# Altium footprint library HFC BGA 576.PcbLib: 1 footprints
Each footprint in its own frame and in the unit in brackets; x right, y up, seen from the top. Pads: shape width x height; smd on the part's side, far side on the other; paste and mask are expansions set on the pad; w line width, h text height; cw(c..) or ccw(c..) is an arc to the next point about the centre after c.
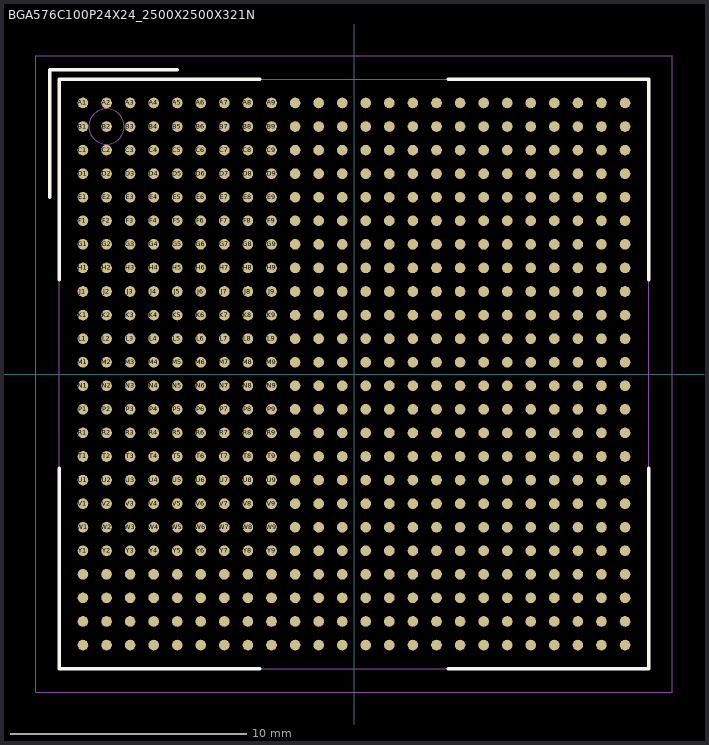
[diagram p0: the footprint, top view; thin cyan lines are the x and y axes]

## BGA576C100P24X24_2500X2500X321N [mm] "576-BGA, collapsing, 1.00 mm pitch, 25.00 X 25.00 X 3.21 mm body"
height 3.21
pads (576):
  round 0.45 smd mask+0.05: A1(-11.5,11.5) A2(-10.5,11.5) A3(-9.5,11.5) A4(-8.5,11.5) A5(-7.5,11.5) A6(-6.5,11.5) A7(-5.5,11.5) A8(-4.5,11.5) A9(-3.5,11.5) A10(-2.5,11.5) A11(-1.5,11.5) A12(-0.5,11.5) A13(0.5,11.5) A14(1.5,11.5) A15(2.5,11.5) A16(3.5,11.5) A17(4.5,11.5) A18(5.5,11.5) A19(6.5,11.5) A20(7.5,11.5) A21(8.5,11.5) A22(9.5,11.5) A23(10.5,11.5) A24(11.5,11.5) AA1(-11.5,-8.5) AA2(-10.5,-8.5) AA3(-9.5,-8.5) AA4(-8.5,-8.5) AA5(-7.5,-8.5) AA6(-6.5,-8.5) AA7(-5.5,-8.5) AA8(-4.5,-8.5) AA9(-3.5,-8.5) AA10(-2.5,-8.5) AA11(-1.5,-8.5) AA12(-0.5,-8.5) AA13(0.5,-8.5) AA14(1.5,-8.5) AA15(2.5,-8.5) AA16(3.5,-8.5) AA17(4.5,-8.5) AA18(5.5,-8.5) AA19(6.5,-8.5) AA20(7.5,-8.5) AA21(8.5,-8.5) AA22(9.5,-8.5) AA23(10.5,-8.5) AA24(11.5,-8.5) AB1(-11.5,-9.5) AB2(-10.5,-9.5) AB3(-9.5,-9.5) AB4(-8.5,-9.5) AB5(-7.5,-9.5) AB6(-6.5,-9.5) AB7(-5.5,-9.5) AB8(-4.5,-9.5) AB9(-3.5,-9.5) AB10(-2.5,-9.5) AB11(-1.5,-9.5) AB12(-0.5,-9.5) AB13(0.5,-9.5) AB14(1.5,-9.5) AB15(2.5,-9.5) AB16(3.5,-9.5) AB17(4.5,-9.5) AB18(5.5,-9.5) AB19(6.5,-9.5) AB20(7.5,-9.5) AB21(8.5,-9.5) AB22(9.5,-9.5) AB23(10.5,-9.5) AB24(11.5,-9.5) AC1(-11.5,-10.5) AC2(-10.5,-10.5) AC3(-9.5,-10.5) AC4(-8.5,-10.5) AC5(-7.5,-10.5) AC6(-6.5,-10.5) AC7(-5.5,-10.5) AC8(-4.5,-10.5) AC9(-3.5,-10.5) AC10(-2.5,-10.5) AC11(-1.5,-10.5) AC12(-0.5,-10.5) AC13(0.5,-10.5) AC14(1.5,-10.5) AC15(2.5,-10.5) AC16(3.5,-10.5) AC17(4.5,-10.5) AC18(5.5,-10.5) AC19(6.5,-10.5) AC20(7.5,-10.5) AC21(8.5,-10.5) AC22(9.5,-10.5) AC23(10.5,-10.5) AC24(11.5,-10.5) AD1(-11.5,-11.5) AD2(-10.5,-11.5) AD3(-9.5,-11.5) AD4(-8.5,-11.5) AD5(-7.5,-11.5) AD6(-6.5,-11.5) AD7(-5.5,-11.5) AD8(-4.5,-11.5) AD9(-3.5,-11.5) AD10(-2.5,-11.5) AD11(-1.5,-11.5) AD12(-0.5,-11.5) AD13(0.5,-11.5) AD14(1.5,-11.5) AD15(2.5,-11.5) AD16(3.5,-11.5) AD17(4.5,-11.5) AD18(5.5,-11.5) AD19(6.5,-11.5) AD20(7.5,-11.5) AD21(8.5,-11.5) AD22(9.5,-11.5) AD23(10.5,-11.5) AD24(11.5,-11.5) B1(-11.5,10.5) B2(-10.5,10.5) B3(-9.5,10.5) B4(-8.5,10.5) B5(-7.5,10.5) B6(-6.5,10.5) B7(-5.5,10.5) B8(-4.5,10.5) B9(-3.5,10.5) B10(-2.5,10.5) B11(-1.5,10.5) B12(-0.5,10.5) B13(0.5,10.5) B14(1.5,10.5) B15(2.5,10.5) B16(3.5,10.5) B17(4.5,10.5) B18(5.5,10.5) B19(6.5,10.5) B20(7.5,10.5) B21(8.5,10.5) B22(9.5,10.5) B23(10.5,10.5) B24(11.5,10.5) C1(-11.5,9.5) C2(-10.5,9.5) C3(-9.5,9.5) C4(-8.5,9.5) C5(-7.5,9.5) C6(-6.5,9.5) C7(-5.5,9.5) C8(-4.5,9.5) C9(-3.5,9.5) C10(-2.5,9.5) C11(-1.5,9.5) C12(-0.5,9.5) C13(0.5,9.5) C14(1.5,9.5) C15(2.5,9.5) C16(3.5,9.5) C17(4.5,9.5) C18(5.5,9.5) C19(6.5,9.5) C20(7.5,9.5) C21(8.5,9.5) C22(9.5,9.5) C23(10.5,9.5) C24(11.5,9.5) D1(-11.5,8.5) D2(-10.5,8.5) D3(-9.5,8.5) D4(-8.5,8.5) D5(-7.5,8.5) D6(-6.5,8.5) D7(-5.5,8.5) D8(-4.5,8.5) D9(-3.5,8.5) D10(-2.5,8.5) D11(-1.5,8.5) D12(-0.5,8.5) D13(0.5,8.5) D14(1.5,8.5) D15(2.5,8.5) D16(3.5,8.5) D17(4.5,8.5) D18(5.5,8.5) D19(6.5,8.5) D20(7.5,8.5) D21(8.5,8.5) D22(9.5,8.5) D23(10.5,8.5) D24(11.5,8.5) E1(-11.5,7.5) E2(-10.5,7.5) E3(-9.5,7.5) E4(-8.5,7.5) E5(-7.5,7.5) E6(-6.5,7.5) E7(-5.5,7.5) E8(-4.5,7.5) E9(-3.5,7.5) E10(-2.5,7.5) E11(-1.5,7.5) E12(-0.5,7.5) E13(0.5,7.5) E14(1.5,7.5) E15(2.5,7.5) E16(3.5,7.5) E17(4.5,7.5) E18(5.5,7.5) E19(6.5,7.5) E20(7.5,7.5) E21(8.5,7.5) E22(9.5,7.5) E23(10.5,7.5) E24(11.5,7.5) F1(-11.5,6.5) F2(-10.5,6.5) F3(-9.5,6.5) F4(-8.5,6.5) F5(-7.5,6.5) F6(-6.5,6.5) F7(-5.5,6.5) F8(-4.5,6.5) F9(-3.5,6.5) F10(-2.5,6.5) F11(-1.5,6.5) F12(-0.5,6.5) F13(0.5,6.5) F14(1.5,6.5) F15(2.5,6.5) F16(3.5,6.5) F17(4.5,6.5) F18(5.5,6.5) F19(6.5,6.5) F20(7.5,6.5) F21(8.5,6.5) F22(9.5,6.5) F23(10.5,6.5) F24(11.5,6.5) G1(-11.5,5.5) G2(-10.5,5.5) G3(-9.5,5.5) G4(-8.5,5.5) G5(-7.5,5.5) G6(-6.5,5.5) G7(-5.5,5.5) G8(-4.5,5.5) G9(-3.5,5.5) G10(-2.5,5.5) G11(-1.5,5.5) G12(-0.5,5.5) G13(0.5,5.5) G14(1.5,5.5) G15(2.5,5.5) G16(3.5,5.5) G17(4.5,5.5) G18(5.5,5.5) G19(6.5,5.5) G20(7.5,5.5) G21(8.5,5.5) G22(9.5,5.5) G23(10.5,5.5) G24(11.5,5.5) H1(-11.5,4.5) H2(-10.5,4.5) H3(-9.5,4.5) H4(-8.5,4.5) H5(-7.5,4.5) H6(-6.5,4.5) H7(-5.5,4.5) H8(-4.5,4.5) H9(-3.5,4.5) H10(-2.5,4.5) H11(-1.5,4.5) H12(-0.5,4.5) H13(0.5,4.5) H14(1.5,4.5) H15(2.5,4.5) H16(3.5,4.5) H17(4.5,4.5) H18(5.5,4.5) H19(6.5,4.5) H20(7.5,4.5) H21(8.5,4.5) H22(9.5,4.5) H23(10.5,4.5) H24(11.5,4.5) J1(-11.5,3.5) J2(-10.5,3.5) J3(-9.5,3.5) J4(-8.5,3.5) J5(-7.5,3.5) J6(-6.5,3.5) J7(-5.5,3.5) J8(-4.5,3.5) J9(-3.5,3.5) J10(-2.5,3.5) J11(-1.5,3.5) J12(-0.5,3.5) J13(0.5,3.5) J14(1.5,3.5) J15(2.5,3.5) J16(3.5,3.5) J17(4.5,3.5) J18(5.5,3.5) J19(6.5,3.5) J20(7.5,3.5) J21(8.5,3.5) J22(9.5,3.5) J23(10.5,3.5) J24(11.5,3.5) K1(-11.5,2.5) K2(-10.5,2.5) K3(-9.5,2.5) K4(-8.5,2.5) K5(-7.5,2.5) K6(-6.5,2.5) K7(-5.5,2.5) K8(-4.5,2.5) K9(-3.5,2.5) K10(-2.5,2.5) K11(-1.5,2.5) K12(-0.5,2.5) K13(0.5,2.5) K14(1.5,2.5) K15(2.5,2.5) K16(3.5,2.5) K17(4.5,2.5) K18(5.5,2.5) K19(6.5,2.5) K20(7.5,2.5) K21(8.5,2.5) K22(9.5,2.5) K23(10.5,2.5) K24(11.5,2.5) L1(-11.5,1.5) L2(-10.5,1.5) L3(-9.5,1.5) L4(-8.5,1.5) L5(-7.5,1.5) L6(-6.5,1.5) L7(-5.5,1.5) L8(-4.5,1.5) L9(-3.5,1.5) L10(-2.5,1.5) L11(-1.5,1.5) L12(-0.5,1.5) L13(0.5,1.5) L14(1.5,1.5) L15(2.5,1.5) L16(3.5,1.5) L17(4.5,1.5) L18(5.5,1.5) L19(6.5,1.5) L20(7.5,1.5) L21(8.5,1.5) L22(9.5,1.5) L23(10.5,1.5) L24(11.5,1.5) M1(-11.5,0.5) M2(-10.5,0.5) M3(-9.5,0.5) M4(-8.5,0.5) M5(-7.5,0.5) M6(-6.5,0.5) M7(-5.5,0.5) M8(-4.5,0.5) M9(-3.5,0.5) M10(-2.5,0.5) M11(-1.5,0.5) M12(-0.5,0.5) M13(0.5,0.5) M14(1.5,0.5) M15(2.5,0.5) M16(3.5,0.5) M17(4.5,0.5) M18(5.5,0.5) M19(6.5,0.5) M20(7.5,0.5) M21(8.5,0.5) M22(9.5,0.5) M23(10.5,0.5) M24(11.5,0.5) N1(-11.5,-0.5) N2(-10.5,-0.5) N3(-9.5,-0.5) N4(-8.5,-0.5) N5(-7.5,-0.5) N6(-6.5,-0.5) N7(-5.5,-0.5) N8(-4.5,-0.5) N9(-3.5,-0.5) N10(-2.5,-0.5) N11(-1.5,-0.5) N12(-0.5,-0.5) N13(0.5,-0.5) N14(1.5,-0.5) N15(2.5,-0.5) N16(3.5,-0.5) N17(4.5,-0.5) N18(5.5,-0.5) N19(6.5,-0.5) N20(7.5,-0.5) N21(8.5,-0.5) N22(9.5,-0.5) N23(10.5,-0.5) N24(11.5,-0.5) P1(-11.5,-1.5) P2(-10.5,-1.5) P3(-9.5,-1.5) P4(-8.5,-1.5) P5(-7.5,-1.5) P6(-6.5,-1.5) P7(-5.5,-1.5) P8(-4.5,-1.5) P9(-3.5,-1.5) P10(-2.5,-1.5) P11(-1.5,-1.5) P12(-0.5,-1.5) P13(0.5,-1.5) P14(1.5,-1.5) P15(2.5,-1.5) P16(3.5,-1.5) P17(4.5,-1.5) P18(5.5,-1.5) P19(6.5,-1.5) P20(7.5,-1.5) P21(8.5,-1.5) P22(9.5,-1.5) P23(10.5,-1.5) P24(11.5,-1.5) R1(-11.5,-2.5) R2(-10.5,-2.5) R3(-9.5,-2.5) R4(-8.5,-2.5) R5(-7.5,-2.5) R6(-6.5,-2.5) R7(-5.5,-2.5) R8(-4.5,-2.5) R9(-3.5,-2.5) R10(-2.5,-2.5) R11(-1.5,-2.5) R12(-0.5,-2.5) R13(0.5,-2.5) R14(1.5,-2.5) R15(2.5,-2.5) R16(3.5,-2.5) R17(4.5,-2.5) R18(5.5,-2.5) R19(6.5,-2.5) R20(7.5,-2.5) R21(8.5,-2.5) R22(9.5,-2.5) R23(10.5,-2.5) R24(11.5,-2.5) T1(-11.5,-3.5) T2(-10.5,-3.5) T3(-9.5,-3.5) T4(-8.5,-3.5) T5(-7.5,-3.5) T6(-6.5,-3.5) T7(-5.5,-3.5) T8(-4.5,-3.5) T9(-3.5,-3.5) T10(-2.5,-3.5) T11(-1.5,-3.5) T12(-0.5,-3.5) T13(0.5,-3.5) T14(1.5,-3.5) T15(2.5,-3.5) T16(3.5,-3.5) T17(4.5,-3.5) T18(5.5,-3.5) T19(6.5,-3.5) T20(7.5,-3.5) T21(8.5,-3.5) T22(9.5,-3.5) T23(10.5,-3.5) T24(11.5,-3.5) U1(-11.5,-4.5) U2(-10.5,-4.5) U3(-9.5,-4.5) U4(-8.5,-4.5) U5(-7.5,-4.5) U6(-6.5,-4.5) U7(-5.5,-4.5) U8(-4.5,-4.5) U9(-3.5,-4.5) U10(-2.5,-4.5) U11(-1.5,-4.5) U12(-0.5,-4.5) U13(0.5,-4.5) U14(1.5,-4.5) U15(2.5,-4.5) U16(3.5,-4.5) U17(4.5,-4.5) U18(5.5,-4.5) U19(6.5,-4.5) U20(7.5,-4.5) U21(8.5,-4.5) U22(9.5,-4.5) U23(10.5,-4.5) U24(11.5,-4.5) V1(-11.5,-5.5) V2(-10.5,-5.5) V3(-9.5,-5.5) V4(-8.5,-5.5) V5(-7.5,-5.5) V6(-6.5,-5.5) V7(-5.5,-5.5) V8(-4.5,-5.5) V9(-3.5,-5.5) V10(-2.5,-5.5) V11(-1.5,-5.5) V12(-0.5,-5.5) V13(0.5,-5.5) V14(1.5,-5.5) V15(2.5,-5.5) V16(3.5,-5.5) V17(4.5,-5.5) V18(5.5,-5.5) V19(6.5,-5.5) V20(7.5,-5.5) V21(8.5,-5.5) V22(9.5,-5.5) V23(10.5,-5.5) V24(11.5,-5.5) W1(-11.5,-6.5) W2(-10.5,-6.5) W3(-9.5,-6.5) W4(-8.5,-6.5) W5(-7.5,-6.5) W6(-6.5,-6.5) W7(-5.5,-6.5) W8(-4.5,-6.5) W9(-3.5,-6.5) W10(-2.5,-6.5) W11(-1.5,-6.5) W12(-0.5,-6.5) W13(0.5,-6.5) W14(1.5,-6.5) W15(2.5,-6.5) W16(3.5,-6.5) W17(4.5,-6.5) W18(5.5,-6.5) W19(6.5,-6.5) W20(7.5,-6.5) W21(8.5,-6.5) W22(9.5,-6.5) W23(10.5,-6.5) W24(11.5,-6.5) Y1(-11.5,-7.5) Y2(-10.5,-7.5) Y3(-9.5,-7.5) Y4(-8.5,-7.5) Y5(-7.5,-7.5) Y6(-6.5,-7.5) Y7(-5.5,-7.5) Y8(-4.5,-7.5) Y9(-3.5,-7.5) Y10(-2.5,-7.5) Y11(-1.5,-7.5) Y12(-0.5,-7.5) Y13(0.5,-7.5) Y14(1.5,-7.5) Y15(2.5,-7.5) Y16(3.5,-7.5) Y17(4.5,-7.5) Y18(5.5,-7.5) Y19(6.5,-7.5) Y20(7.5,-7.5) Y21(8.5,-7.5) Y22(9.5,-7.5) Y23(10.5,-7.5) Y24(11.5,-7.5)
Top Overlay:
  lines w0.15: -12.9,7.5 -12.9,12.9 -7.5,12.9 ; -12.5,-4 -12.5,-12.5 -4,-12.5 ; -12.5,4 -12.5,12.5 -4,12.5 ; 4,-12.5 12.5,-12.5 12.5,-4 ; 4,12.5 12.5,12.5 12.5,4
Top Assembly:
  circle w0: c-10.5,10.5 r0.75
  lines w0: -12.5,-12.5 12.5,-12.5 12.5,12.5 -12.5,12.5 -12.5,-12.5
  text ".Designator" at -2.621,-0.355 h1.52
Top Courtyard:
  lines w0.05: -13.5,-13.5 13.5,-13.5 13.5,13.5 -13.5,13.5 -13.5,-13.5
3D body "BGA576C100P24X24_2500X2500X321.STEP": height 3.21, standoff 0, extent -12.5,-12.5 12.5,12.5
